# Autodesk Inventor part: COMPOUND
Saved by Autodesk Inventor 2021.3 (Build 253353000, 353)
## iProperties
Created: 2022-06
Part Number: COMPOUND
Material: Generic
Document SubType Name: Modeling
Designer: Administrator
Density: 1 g/cm^3
Appearance: Default
Title: COMPOUND
Author: Administrator
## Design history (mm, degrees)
feature "Body1"
feature "Body2"
feature "Body3"
feature "Body4"
feature "Body5"
feature "Body6"
feature "Body7"
feature "Body8"
feature "Body9"
feature "Body10"
feature "Body11"
feature "Body12"
feature "Body13"
feature "Body14"
feature "Body15"
feature "Body16"
feature "Body17"
body "Solid1"
body "Solid2"
body "Solid3"
body "Solid4"
body "Solid5"
body "Solid6"
body "Solid7"
body "Solid8"
body "Solid9"
body "Solid10"
body "Solid11"
body "Solid12"
body "Solid13"
body "Solid14"
body "Solid15"
body "Solid16"
body "Solid17"
